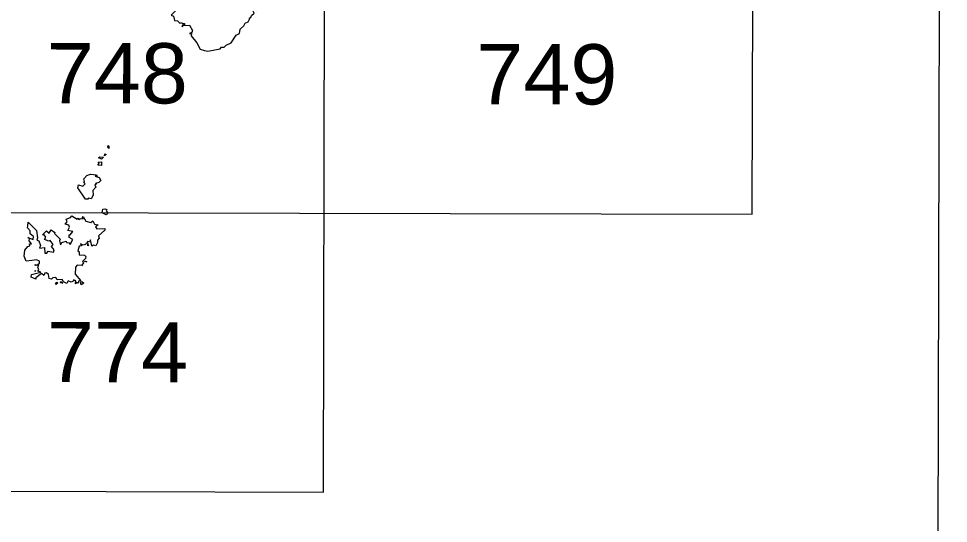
# Model space of a CAD drawing. Extents: x 480264 to 484872, y 4381275 to 4384491.
# Drawn here: x 484571 to 484871.9, y 4383064.8 to 4383228.3 of the extents above; entities that cross this region are included whole.
import ezdxf
from ezdxf.enums import TextEntityAlignment as Align

# ---------------------------------------------------------------- set-up
doc = ezdxf.new("R2010")
doc.units = 0
doc.header["$LTSCALE"] = 4
doc.linetypes.add('DOTTED', pattern=[1.5, 0.3, -1.2])
for name, color, linetype, lineweight in [('1', 7, 'Continuous', 13), ('2', 7, 'DOTTED', 13), ('3', 7, 'Continuous', 25)]:
    doc.layers.add(name, color=color, linetype=linetype, lineweight=lineweight)

msp = doc.modelspace()

# ---------------------------------------------------------------- linework, layer by layer
at = {"layer": '1', "lineweight": 25}
for p, q in [((484669.63, 4383074.95), (484670.92, 4383616.9)), ((484808.41, 4383164.93), (484809.48, 4383616.57)), ((484531.29, 4383165.59), (484808.41, 4383164.93)), ((484531.07, 4383075.27), (484669.63, 4383074.94))]:
    msp.add_line(p, q, dxfattribs=at)
msp.add_lwpolyline([(480271.92, 4384491.35), (484871.91, 4384480.42), (484864.3, 4381275.43), (480264.31, 4381286.36)], close=True, dxfattribs=at)
at = {"layer": '3'}
for points in [[(484621.21, 4383231.57), (484621.74, 4383230.75), (484620.38, 4383229.39), (484621.09, 4383229.1), (484621.44, 4383227.65), (484622.42, 4383227.5), (484623.19, 4383226.82), (484623.76, 4383227.06), (484623.87, 4383226.63), (484624.54, 4383226.63), (484624.8, 4383226.39), (484624.38, 4383225.99), (484626.32, 4383226.18), (484627.2, 4383224.46), (484627, 4383223.81), (484626.23, 4383223.4), (484626.92, 4383223.43), (484626.8, 4383222.74), (484628.6, 4383220.45)], [(484643.82, 4383225.88), (484644.27, 4383226.77), (484645.22, 4383227.2), (484645.85, 4383228.28), (484645.57, 4383228.4), (484646.16, 4383228.62), (484646.31, 4383229.23), (484647.23, 4383230.01), (484646.64, 4383231.14), (484647.86, 4383230.84), (484648.82, 4383231.74), (484648.75, 4383233.04), (484649.71, 4383233.1), (484651.21, 4383234.24)], [(484628.6, 4383220.45), (484629.75, 4383218.37), (484631.12, 4383217.92), (484632.18, 4383217.73), (484636.17, 4383218.46), (484636.64, 4383219.02), (484637.55, 4383219.01), (484638.13, 4383219.7), (484639.71, 4383220.38), (484641.34, 4383222.92), (484642.43, 4383223.47), (484642.66, 4383224.8), (484643.82, 4383225.88)], [(484594.48, 4383169.92), (484593.55, 4383170.17), (484593.36, 4383169.8), (484592.61, 4383169.78), (484590.1, 4383173.44), (484590.34, 4383174.4), (484591.74, 4383174.05), (484592.49, 4383174.73), (484591.92, 4383175.28), (484592.28, 4383175.52), (484592.09, 4383176.4), (484593.06, 4383177.47)], [(484593.06, 4383177.47), (484594.23, 4383177.86), (484596.14, 4383177.71), (484596.38, 4383177.2), (484595.77, 4383177.21), (484597, 4383176.8), (484597.55, 4383175.82), (484596.94, 4383175.21), (484595.84, 4383174.92), (484596.14, 4383174.74), (484595.66, 4383174.39), (484596.01, 4383173.65), (484595, 4383172.61), (484595.13, 4383171.13), (484594.48, 4383169.92)], [(484598.03, 4383165.34), (484598.19, 4383166.59), (484598.91, 4383166.69), (484599.52, 4383166.46), (484599.32, 4383166.05), (484599.79, 4383165.35)], [(484599.79, 4383165.35), (484599.28, 4383164.77), (484598.03, 4383165.34)], [(484573.92, 4383161.16), (484574.1, 4383162.35), (484576.75, 4383159.6), (484577.11, 4383157.22), (484576.87, 4383156.48), (484577.55, 4383156.29), (484578.07, 4383154.82), (484577.75, 4383153.9), (484579.33, 4383154.17), (484579.47, 4383152.31), (484580.14, 4383152.35), (484580.54, 4383153), (484582.22, 4383152.65), (484582.43, 4383153.41)], [(484587.61, 4383158.23), (484588.48, 4383159.3), (484586.9, 4383159.65), (484587.41, 4383160.7), (484587.18, 4383161.35), (484586.08, 4383161.69), (484586.69, 4383162.47), (484586.33, 4383163.29), (484587.81, 4383163.85), (484588.15, 4383164.4), (484589.94, 4383163.31)], [(484589.94, 4383163.31), (484590.15, 4383163.62), (484590.45, 4383163.16), (484590.87, 4383163.52), (484591.83, 4383163.41), (484591.49, 4383163.8), (484591.82, 4383164.21), (484592.75, 4383162.67), (484594.32, 4383162.19), (484594.97, 4383162.82), (484595.51, 4383161.71), (484596.68, 4383161.53), (484595.83, 4383160.87), (484596.23, 4383160.18), (484598.87, 4383160.3), (484598.85, 4383159.71), (484596.84, 4383157.95), (484597.01, 4383157.16), (484596.48, 4383156.55), (484596.53, 4383155.73)], [(484575.21, 4383149.97), (484573.41, 4383149.7), (484572.8, 4383151.36), (484572.98, 4383153.27), (484573.9, 4383154.48), (484574.64, 4383154.72), (484574.49, 4383155.37), (484575.19, 4383155.38), (484574.36, 4383156.32), (484574.52, 4383156.93), (484573.94, 4383157.38), (484575.66, 4383156.72), (484575.75, 4383157.7), (484574.74, 4383158.61), (484574.66, 4383159.58), (484573.84, 4383160.47), (484573.92, 4383161.16)], [(484582.43, 4383153.41), (484581.64, 4383154.51), (484582.14, 4383155.16), (484581.19, 4383156.46), (484580.8, 4383156.18), (484579.31, 4383156.71), (484579.8, 4383157.48), (484579.25, 4383158.22), (484578.68, 4383158.21), (484579.99, 4383159.49), (484580.89, 4383158.83), (484581.47, 4383159.85)], [(484581.47, 4383159.85), (484582.74, 4383159.03), (484582.6, 4383158.72), (484584.45, 4383156.84), (484584.23, 4383156.31), (484584.54, 4383154.99), (484584.91, 4383155.73), (484586.41, 4383156.22), (484586.48, 4383155.72), (484587.35, 4383155.67), (484587.65, 4383155.06), (484588.49, 4383156.74), (484587.29, 4383157.39), (484587.37, 4383158.29), (484587.61, 4383158.23)], [(484596.53, 4383155.73), (484595.96, 4383154.69), (484595.2, 4383154.91), (484594.65, 4383154.55), (484594.28, 4383156.66), (484593.94, 4383155.94), (484593.16, 4383156.11), (484593.4, 4383155.39), (484592.79, 4383155.59), (484592.62, 4383155.16), (484591.82, 4383154.93), (484591.05, 4383155.31), (484591.28, 4383154.66), (484590.56, 4383154.56), (484590.18, 4383153.03), (484590.53, 4383152.7), (484590.53, 4383151.72)], [(484590.53, 4383151.72), (484592.3, 4383151.67), (484592.72, 4383151.19), (484592.64, 4383150.62), (484591.62, 4383149.56), (484591.97, 4383149.13), (484591.41, 4383148.45), (484591.66, 4383148.28), (484589.88, 4383148.37), (484589.43, 4383147.78), (484589.32, 4383145.54), (484591.09, 4383143.38), (484590.33, 4383143.25), (484590.23, 4383142.62), (484589.85, 4383142.79), (484589.38, 4383142.38), (484589.45, 4383143.38), (484588.72, 4383143.71)], [(484578.37, 4383145.77), (484576.49, 4383144.34), (484576.5, 4383143.85), (484575, 4383144.54), (484575.17, 4383145.35), (484578.2, 4383146.11), (484577.14, 4383146.52), (484577.53, 4383146.92), (484577.2, 4383147.74), (484577.54, 4383148.4), (484576.3, 4383148.3), (484576.36, 4383148.61), (484576.91, 4383148.42), (484577.76, 4383149.03), (484577.77, 4383149.69), (484576.72, 4383150.12), (484575.21, 4383149.97)], [(484588.72, 4383143.71), (484588.88, 4383143.38), (484587.94, 4383142.91), (484587.04, 4383143.39), (484586.52, 4383142.49), (484585.48, 4383143.01), (484585.04, 4383143.74), (484583.44, 4383143.65), (484583.06, 4383144.42), (484581.99, 4383144.32), (484581.59, 4383143.87), (484580.85, 4383144.13), (484580.64, 4383145.41), (484579.94, 4383145.9), (484579.4, 4383145.81), (484579.08, 4383145.07), (484578.37, 4383145.77)]]:
    msp.add_lwpolyline(points, dxfattribs=at)
for points in [[(484623.86, 4383226.03), (484623.87, 4383225.65), (484624.21, 4383226.02)], [(484599.95, 4383187.15), (484599.69, 4383186.63), (484600.24, 4383186.34), (484600.4, 4383186.66)], [(484597.29, 4383183.48), (484598.42, 4383183.39), (484597.84, 4383182.71), (484596.77, 4383183.19)], [(484598.87, 4383184.44), (484599.27, 4383184.29), (484598.76, 4383183.85)], [(484597.82, 4383181.92), (484597.83, 4383180.65), (484596.64, 4383180.77), (484597.03, 4383181.31), (484596.71, 4383181.76)], [(484593.6, 4383155.03), (484593.4, 4383154.72), (484593.32, 4383155.18)], [(484592.61, 4383149.76), (484593.05, 4383149.55), (484592.25, 4383149.63)], [(484576.36, 4383146.73), (484576.58, 4383146.53), (484576.2, 4383146.5)], [(484582.94, 4383142.4), (484583.32, 4383142.92), (484583.64, 4383142.67), (484583.14, 4383142.2)], [(484584.55, 4383142.74), (484584.58, 4383143.12), (484585.24, 4383142.63)], [(484591.45, 4383143.09), (484592.1, 4383142.57), (484591.2, 4383142.08), (484591, 4383142.96)]]:
    msp.add_lwpolyline(points, close=True, dxfattribs=at)

# ---------------------------------------------------------------- texts
at = {"layer": '2', "width": 1.05}
for s, p in [('748', (484602.892, 4383200.834)), ('749', (484741.912, 4383200.504)), ('774', (484602.942, 4383110.494))]:
    msp.add_text(s, height=19.5, rotation=359.864, dxfattribs=at).set_placement(p, align=Align.CENTER)

doc.saveas('drawing.dxf')
